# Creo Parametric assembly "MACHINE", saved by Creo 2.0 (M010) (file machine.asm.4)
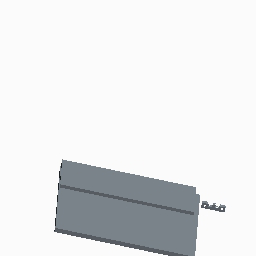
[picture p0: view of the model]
Units: Inch lbm Second (Pro/E Default); INCH, POUND, SECS

Created from: INLBS_ASM_DESIGN.ASM

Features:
  1. datum plane "ASM_RIGHT"
  2. datum plane "ASM_TOP"
  3. datum plane "ASM_FRONT"
  4. coordinate system
  5. component "YMOTOR"
  6. coordinate system
  7. component "BASE_BOARD"
  8. component "TOPBOARD"

Other named items: ACS0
